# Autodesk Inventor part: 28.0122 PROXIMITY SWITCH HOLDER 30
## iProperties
Created: 2007-05
Part Number: 28.0122 PROXIMITY SWITCH HOLDER 30
Document SubType Name: Modeling
Designer: Andy Moles
Material: Acetal Resin, Black
Density: 1.425 g/cm^3
Author: Andy Moles
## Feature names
1. Extrusion1
2. Extrusion2
3. Extrusion3
4. Extrusion4
5. Extrusion5
